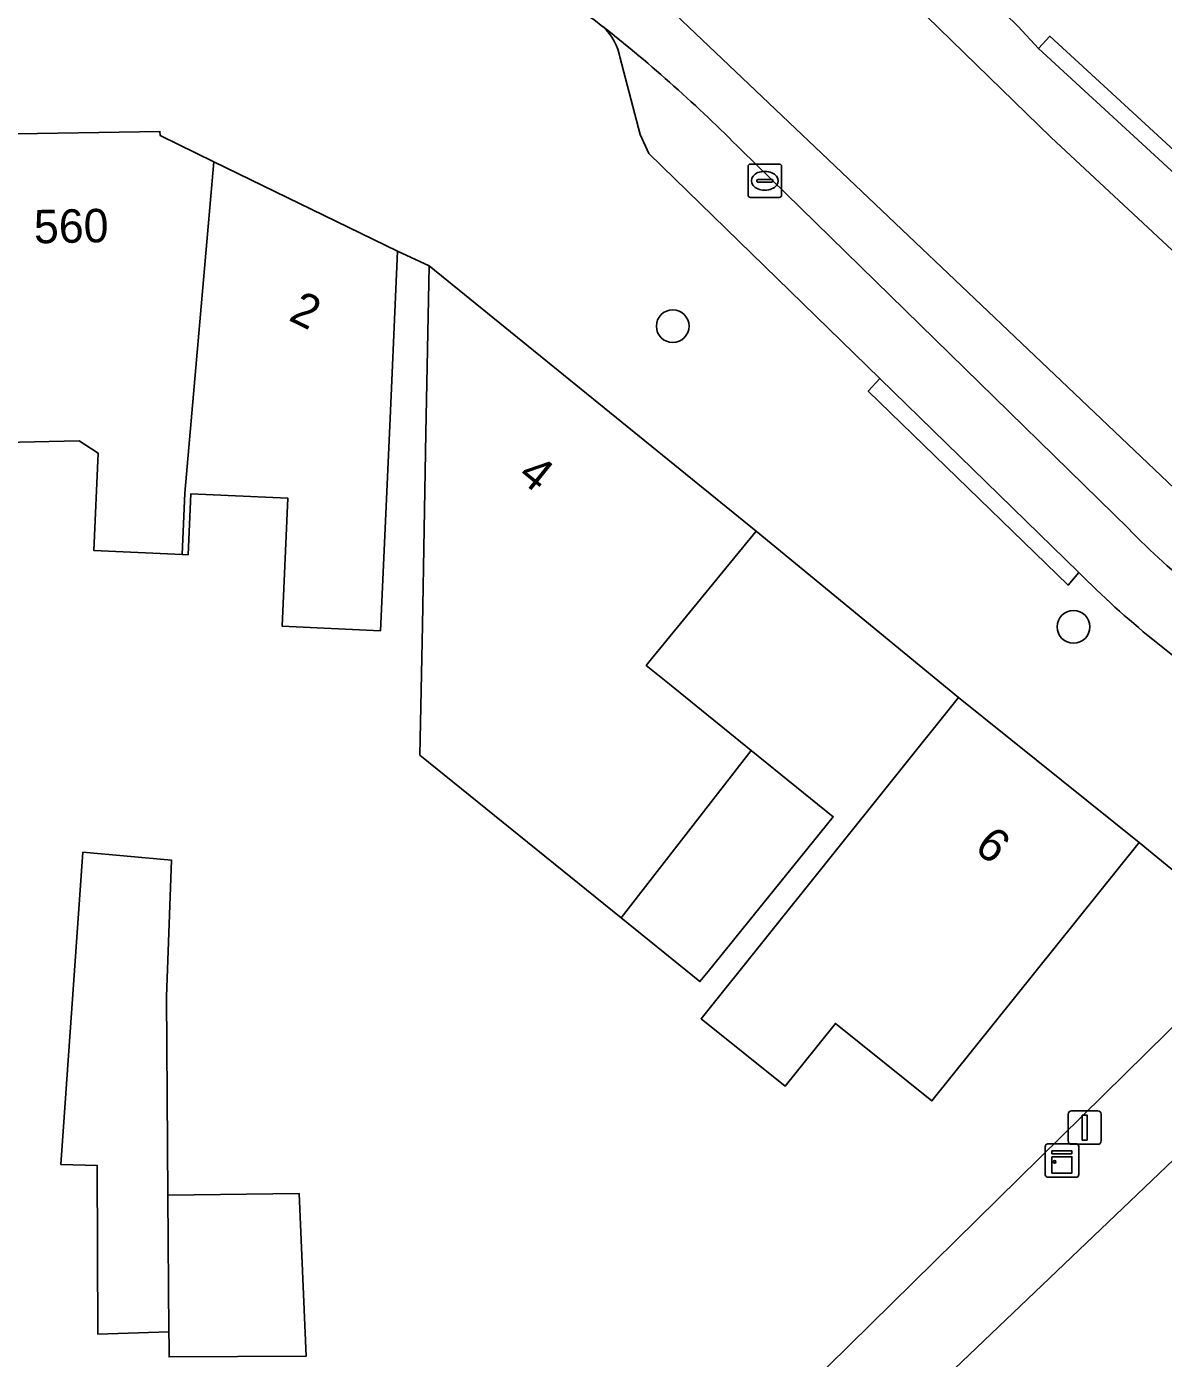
# Model space of a CAD drawing. Extents: x 162879 to 165540, y 384011 to 385181.
# Drawn here: x 164079.05 to 164113.04, y 384285.92 to 384325.72 of the extents above; entities that cross this region are included whole.
import ezdxf

# ---------------------------------------------------------------- set-up
doc = ezdxf.new("R2010")
doc.units = 0
for name, color, linetype in [('IMGEO_Boom', 7, 'Continuous'), ('IMGEO_Erf', 7, 'Continuous'), ('IMGEO_Kast', 7, 'Continuous'), ('IMGEO_Kolk', 7, 'Continuous'), ('IMGEO_Lichtmast', 7, 'Continuous'), ('IMGEO_Pand', 7, 'Continuous'), ('IMGEO_Pand_nummerreeks', 7, 'Continuous'), ('IMGEO_Parkeervlak_open', 7, 'Continuous'), ('IMGEO_Rijbaan_lokaal_gesloten', 7, 'Continuous'), ('IMGEO_Voetpad_open', 7, 'Continuous')]:
    doc.layers.add(name, color=color, linetype=linetype)

msp = doc.modelspace()

# ---------------------------------------------------------------- linework, layer by layer
at = {"layer": 'IMGEO_Boom'}
for centre in [(164098.368, 384316.769), (164110.353, 384307.78)]:
    msp.add_circle(centre, 0.489, dxfattribs=at)
at = {"layer": 'IMGEO_Erf'}
for points in [[(164115.492, 384298.721), (164112.317, 384301.335), (164106.121, 384293.611), (164103.233, 384295.927), (164101.731, 384294.053), (164099.218, 384296.069), (164106.917, 384305.666), (164100.864, 384310.637), (164097.694, 384306.771), (164097.576, 384306.628), (164098.271, 384306.066), (164100.715, 384304.089), (164103.167, 384302.107), (164099.426, 384297.481), (164099.179, 384297.176), (164096.823, 384299.082), (164094.283, 384301.136), (164090.808, 384303.947), (164090.881, 384307.831), (164090.989, 384313.572), (164091.086, 384318.571), (164090.137, 384319.006), (164089.914, 384314.011), (164089.63, 384307.667), (164086.687, 384307.803), (164086.863, 384311.624), (164083.959, 384311.759), (164083.875, 384309.936), (164083.697, 384309.944), (164081.053, 384310.066), (164081.187, 384312.977), (164080.616, 384313.343), (164078.387, 384313.294)], [(164094.153, 384276.963), (164113.789, 384296.288)]]:
    msp.add_lwpolyline(points, dxfattribs=at)
msp.add_lwpolyline([(164080.726, 384301.044), (164083.376, 384300.812), (164083.232, 384296.735), (164083.275, 384290.79), (164087.194, 384290.848), (164087.412, 384285.985), (164083.31, 384285.958), (164083.307, 384286.305), (164083.304, 384286.705), (164081.173, 384286.643), (164081.159, 384291.683), (164080.075, 384291.711)], close=True, dxfattribs=at)
at = {"layer": 'IMGEO_Kast'}
for p, q in [((164109.51, 384291.403), (164109.51, 384292.244)), ((164109.51, 384292.244), (164109.51, 384291.403)), ((164109.585, 384292.328), (164110.426, 384292.328)), ((164110.426, 384292.328), (164109.585, 384292.328)), ((164110.51, 384292.253), (164110.51, 384291.412)), ((164110.51, 384291.412), (164110.51, 384292.253)), ((164110.435, 384291.328), (164109.594, 384291.328)), ((164109.594, 384291.328), (164110.435, 384291.328))]:
    msp.add_line(p, q, dxfattribs=at)
for points in [[(164109.705, 384292.118), (164110.305, 384292.118), (164110.305, 384292.033), (164109.705, 384292.033), (164109.705, 384292.118)], [(164109.705, 384291.943), (164110.305, 384291.943), (164110.305, 384291.454), (164109.705, 384291.454), (164109.705, 384291.943)]]:
    msp.add_lwpolyline(points, dxfattribs=at)
msp.add_circle((164109.789, 384291.792), 0.0377, dxfattribs=at)
for centre, start, end in [((164109.588, 384292.25), 92.4484, 184.2845), ((164109.588, 384292.25), 92.4484, 184.2845), ((164110.432, 384292.25), 2.4484, 94.2845), ((164110.432, 384292.25), 2.4484, 94.2845), ((164109.588, 384291.406), 182.4484, 274.2845), ((164109.588, 384291.406), 182.4484, 274.2845), ((164110.432, 384291.406), 272.4484, 4.2845), ((164110.432, 384291.406), 272.4484, 4.2845)]:
    msp.add_arc(centre, 0.0779, start, end, dxfattribs=at)
at = {"layer": 'IMGEO_Kolk'}
for p, q in [((164100.621, 384320.688), (164100.621, 384321.54)), ((164100.696, 384321.614), (164101.548, 384321.614)), ((164101.622, 384321.54), (164101.622, 384320.688)), ((164100.88, 384321.108), (164100.88, 384321.12)), ((164101.318, 384321.071), (164100.92, 384321.071)), ((164100.923, 384321.157), (164101.321, 384321.157)), ((164101.109, 384321.394), (164101.134, 384321.394)), ((164101.364, 384321.12), (164101.364, 384321.108)), ((164101.548, 384320.614), (164100.696, 384320.614)), ((164101.132, 384320.834), (164101.107, 384320.834))]:
    msp.add_line(p, q, dxfattribs=at)
for points in [[(164100.621, 384320.688), (164100.621, 384321.54)], [(164100.696, 384321.614), (164101.548, 384321.614)], [(164101.622, 384321.54), (164101.622, 384320.688)], [(164101.548, 384320.614), (164100.696, 384320.614)]]:
    msp.add_lwpolyline(points, dxfattribs=at)
for centre, radius, start, end in [((164100.698, 384321.538), 0.0765, 91.552, 178.448), ((164100.698, 384321.538), 0.0765, 91.552, 178.448), ((164101.546, 384321.538), 0.0765, 1.552, 88.448), ((164101.546, 384321.538), 0.0765, 1.552, 88.448), ((164100.92, 384321.117), 0.0403, 85.8775, 175.7526), ((164100.917, 384321.107), 0.0366, 178.938, 274.7102), ((164101.321, 384321.114), 0.043, 264.8664, 352.4533), ((164101.325, 384321.119), 0.0386, 1.7309, 96.639), ((164100.698, 384320.69), 0.0765, 181.552, 268.448), ((164100.698, 384320.69), 0.0765, 181.552, 268.448), ((164101.546, 384320.69), 0.0765, 271.552, 358.448), ((164101.546, 384320.69), 0.0765, 271.552, 358.448)]:
    msp.add_arc(centre, radius, start, end, dxfattribs=at)
for centre, major_axis, ratio, start_param, end_param in [((164101.108, 384321.114), (-0.387, 0.002), 0.722429, 4.712389, 7.853982), ((164101.133, 384321.114), (-0.39, 0.002), 0.717154, 1.570796, 4.712389)]:
    msp.add_ellipse(centre, major_axis=major_axis, ratio=ratio, start_param=start_param, end_param=end_param, dxfattribs=at)
at = {"layer": 'IMGEO_Lichtmast'}
for p, q in [((164110.191, 384292.414), (164110.191, 384293.214)), ((164110.191, 384293.214), (164110.191, 384292.414)), ((164110.291, 384293.314), (164111.081, 384293.314)), ((164111.081, 384293.314), (164110.291, 384293.314)), ((164111.181, 384293.214), (164111.181, 384292.414)), ((164111.181, 384292.414), (164111.181, 384293.214)), ((164111.081, 384292.314), (164110.291, 384292.314)), ((164110.291, 384292.314), (164111.081, 384292.314))]:
    msp.add_line(p, q, dxfattribs=at)
msp.add_lwpolyline([(164110.611, 384293.189), (164110.761, 384293.189), (164110.761, 384292.439), (164110.611, 384292.439), (164110.611, 384293.189)], dxfattribs=at)
for centre, start, end in [((164110.291, 384293.214), 90, 180), ((164110.291, 384293.214), 90, 180), ((164111.081, 384293.214), 0, 90), ((164111.081, 384293.214), 360, 90), ((164110.291, 384292.414), 180, 270), ((164110.291, 384292.414), 180, 270), ((164111.081, 384292.414), 270, 0), ((164111.081, 384292.414), 270, 0)]:
    msp.add_arc(centre, 0.1, start, end, dxfattribs=at)
at = {"layer": 'IMGEO_Pand'}
for points in [[(164083.697, 384309.944), (164083.776, 384311.781), (164084.648, 384321.684), (164083.04, 384322.468), (164083.036, 384322.59), (164078.147, 384322.503), (164078.404, 384314.042), (164078.387, 384313.294), (164080.616, 384313.343), (164081.187, 384312.977), (164081.053, 384310.066)], [(164083.697, 384309.944), (164083.875, 384309.936), (164083.959, 384311.759), (164086.863, 384311.624), (164086.687, 384307.803), (164089.63, 384307.667), (164089.914, 384314.011), (164090.137, 384319.006), (164084.648, 384321.684), (164083.776, 384311.781)], [(164100.715, 384304.089), (164098.271, 384306.066), (164097.576, 384306.628), (164097.694, 384306.771), (164100.864, 384310.637), (164091.086, 384318.571), (164090.989, 384313.572), (164090.881, 384307.831), (164090.808, 384303.947), (164094.283, 384301.136), (164096.823, 384299.082)], [(164106.917, 384305.666), (164099.218, 384296.069), (164101.731, 384294.053), (164103.233, 384295.927), (164106.121, 384293.611), (164112.317, 384301.335)], [(164100.715, 384304.089), (164096.823, 384299.082), (164099.179, 384297.176), (164099.426, 384297.481), (164103.167, 384302.107)], [(164083.232, 384296.735), (164083.376, 384300.812), (164080.726, 384301.044), (164080.075, 384291.711), (164081.159, 384291.683), (164081.173, 384286.643), (164083.304, 384286.705), (164083.275, 384290.79)], [(164127.921, 384285.422), (164128.273, 384286.165), (164130.06, 384289.941), (164122.091, 384293.713), (164121.222, 384291.877), (164116.191, 384294.568), (164104.396, 384283.315), (164105.502, 384282.156), (164107.847, 384279.697), (164111.109, 384276.279), (164113.66, 384278.713), (164113.192, 384279.391), (164118.191, 384284.16), (164125.652, 384280.629)], [(164087.194, 384290.848), (164083.275, 384290.79), (164083.304, 384286.705), (164083.307, 384286.305), (164083.31, 384285.958), (164087.412, 384285.985)]]:
    msp.add_lwpolyline(points, close=True, dxfattribs=at)
at = {"layer": 'IMGEO_Parkeervlak_open'}
for points in [[(164096.796, 384324.781), (164097.392, 384322.493), (164097.654, 384321.926), (164104.559, 384315.209), (164110.509, 384309.409)], [(164111.993, 384310.718), (164100.414, 384322.038)]]:
    msp.add_lwpolyline(points, dxfattribs=at)
for centre, radius, start, end in [((164068.4, 384290.289), 45.088, 44.7627, 51.8), ((164095.073, 384324.45), 1.755, 10.8583, 46.3882), ((164129.411, 384327.699), 24.326, 224.2729, 237.7688), ((164130.252, 384328.984), 27.802, 224.7548, 237.1058)]:
    msp.add_arc(centre, radius, start, end, dxfattribs=at)
at = {"layer": 'IMGEO_Rijbaan_lokaal_gesloten'}
for points in [[(164117.754, 384317.402), (164117.468, 384317.634), (164115.039, 384319.73), (164113.769, 384320.96), (164109.302, 384325.065), (164108.695, 384325.723), (164101.439, 384332.813), (164100.288, 384331.601), (164103.358, 384328.579), (164109.687, 384322.406), (164115.908, 384316.623), (164118.995, 384314.012), (164122.11, 384311.551), (164125.404, 384309.308), (164130.616, 384306.277), (164134.306, 384304.491), (164139.38, 384302.587), (164143.428, 384301.217), (164145.28, 384300.663), (164150.597, 384299.412)], [(164150.597, 384299.412), (164145.28, 384300.663), (164143.428, 384301.217), (164139.38, 384302.587), (164134.306, 384304.491), (164130.616, 384306.277), (164125.404, 384309.308), (164122.11, 384311.551), (164118.995, 384314.012), (164115.908, 384316.623), (164109.687, 384322.406), (164103.358, 384328.579), (164100.288, 384331.601), (164096.665, 384327.787), (164115.555, 384309.845), (164121.608, 384305.565), (164126.813, 384302.345), (164132.011, 384299.762), (164137.697, 384297.535), (164141.839, 384296.216), (164147.585, 384294.621)], [(164096.665, 384327.787), (164095.31, 384326.36), (164096.01, 384325.934), (164096.283, 384325.721)], [(164206.411, 384299.729), (164212.508, 384301.669), (164212.859, 384301.79), (164212.252, 384303.452), (164197.812, 384299.009), (164188.317, 384296.456), (164181.548, 384294.891), (164173.847, 384293.566), (164168.66, 384293.088), (164163.876, 384292.878), (164158.942, 384292.968), (164153.617, 384293.6), (164147.585, 384294.621), (164141.839, 384296.216), (164137.697, 384297.535), (164132.011, 384299.762), (164126.813, 384302.345), (164121.608, 384305.565), (164115.555, 384309.845), (164096.665, 384327.787)], [(164100.414, 384322.038), (164111.993, 384310.718)]]:
    msp.add_lwpolyline(points, dxfattribs=at)
for centre, radius, start, end in [((164068.4, 384290.289), 45.088, 44.7627, 51.8), ((164129.411, 384327.699), 24.326, 224.2729, 237.7688)]:
    msp.add_arc(centre, radius, start, end, dxfattribs=at)
at = {"layer": 'IMGEO_Voetpad_open'}
for points in [[(164096.283, 384325.721), (164096.01, 384325.934), (164095.31, 384326.36), (164088.024, 384330.42)], [(164108.695, 384325.723), (164109.302, 384325.065), (164109.64, 384325.433), (164114.107, 384321.328), (164113.769, 384320.96), (164115.039, 384319.73), (164117.468, 384317.634), (164117.754, 384317.402)], [(164110.509, 384309.409), (164110.19, 384309.024), (164104.214, 384314.826), (164104.559, 384315.209), (164097.654, 384321.926), (164097.392, 384322.493), (164096.796, 384324.781)], [(164078.147, 384322.503), (164083.036, 384322.59), (164083.04, 384322.468), (164084.648, 384321.684), (164090.137, 384319.006), (164091.086, 384318.571), (164100.864, 384310.637), (164106.917, 384305.666), (164112.317, 384301.335), (164115.492, 384298.721), (164118.693, 384296.955), (164126.3, 384292.851), (164133.482, 384289.712), (164136.785, 384288.527), (164142.516, 384286.842), (164149.177, 384285.243), (164149.156, 384284.983), (164153.245, 384283.977), (164161.95, 384283.216), (164166.504, 384283.339), (164169.468, 384283.398), (164176.205, 384283.661), (164187.298, 384284.935)], [(164105.502, 384282.156), (164104.396, 384283.315), (164116.191, 384294.568), (164118.693, 384296.955), (164115.492, 384298.721), (164113.789, 384296.288), (164094.153, 384276.963)]]:
    msp.add_lwpolyline(points, dxfattribs=at)
for points in [[(164113.769, 384320.96), (164114.107, 384321.328), (164109.64, 384325.433), (164109.302, 384325.065)], [(164104.559, 384315.209), (164104.214, 384314.826), (164110.19, 384309.024), (164110.509, 384309.409)]]:
    msp.add_lwpolyline(points, close=True, dxfattribs=at)
for centre, radius, start, end in [((164095.073, 384324.45), 1.755, 10.8583, 46.3882), ((164130.252, 384328.984), 27.802, 224.7548, 237.1058)]:
    msp.add_arc(centre, radius, start, end, dxfattribs=at)

# ---------------------------------------------------------------- texts
at = {"layer": 'IMGEO_Pand_nummerreeks'}
for s, rotation, p in [('560', 1.019, (164079.274, 384319.242)), ('2', 333.9963, (164086.847, 384316.962)), ('4', 320.9437, (164093.695, 384312.231)), ('6', 321.2691, (164107.35, 384301.113))]:
    msp.add_text(s, height=1, rotation=rotation, dxfattribs=at).set_placement(p)

doc.saveas('drawing.dxf')
